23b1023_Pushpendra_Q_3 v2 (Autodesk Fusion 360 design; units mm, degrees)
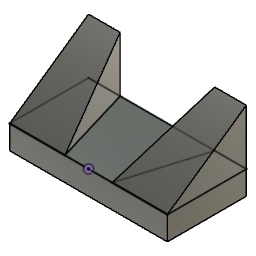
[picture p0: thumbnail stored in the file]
sketch "Sketch1" plane through (0, 0, 0) normal (0, 0, 1) x axis (1, 0, 0)
  line L1 (50, 50) -> (-50, 50)
  line L2 (-50, 0) -> (-50, 50)
  line L3 (50, 0) -> (-50, 0)
  line L4 (50, 0) -> (50, 50)
  line L5 (-30, 50) -> (-50, 50)
  line L6 (30, 50) -> (50, 50)
  line L7 (-15, 0) -> (-50, 0)
  line L8 (15, 0) -> (50, 0)
  line L9 (-30, 50) -> (-15, 0)
  line L10 (30, 50) -> (15, 0)
  point P6 (-30, 50)
  point P7 (30, 50)
  point P8 (-15, 0)
  point P9 (15, 0)
  point P2 (-50, 50)
  point P3 (50, 50)
  point P4 (-50, 0)
  point P5 (50, 0)
  point P1 (0, 0)
  horizontal L1
  perpendicular L1 L2
  perpendicular L2 L3
  perpendicular L3 L4
  coincident L1 P6
  coincident L1 P7
  coincident L3 P8
  coincident L3 P9
  dimension "d1" distance P2 P3 = 100
  dimension "d2" distance P3 P7 = 20
  dimension "d3" distance P2 P6 = 20
  dimension "d4" distance P4 P8 = 35
  dimension "d5" distance P5 P9 = 35
  dimension "d6" distance P1 L1 = 50
  dimension "d7" distance P1 L4 = 50
  dimension "d8" distance P1 L9 = 14.3674
extrude "Extrude1" new body sketch "Sketch1" along normal blind 35
extrude "Extrude3" add sketch "Sketch1" against normal blind 15
sketch "Sketch2" plane through (-50, 0, 0) normal (-1, 0, 0) x axis (0, -1, 0)
  line L1 (0, 35) -> (0, -15)
  line L2 (-50, 35) -> (0, 35)
  line L3 (-50, -15) -> (-50, 35)
  line L4 (0, -15) -> (-50, -15)
  line L5 (0, 0) -> (-50, 35)
  point P4 (-50, 35)
  point P6 (-50, 35)
  point P1 (0, 0)
  point P7 (0, 0)
  coincident P4 P6
  coincident P1 P7
sketch "Sketch3" plane through (50, 0, 0) normal (1, 0, 0) x axis (0, 1, 0)
  line L1 (50, 35) -> (50, -15)
  line L2 (0, 35) -> (50, 35)
  line L3 (0, -15) -> (0, 35)
  line L4 (50, -15) -> (0, -15)
  line L5 (0, 0) -> (50, 35)
  point P3 (50, 35)
  point P6 (50, 35)
  point P1 (0, 0)
  point P7 (0, 0)
  coincident P3 P6
  coincident P1 P7
extrude "Extrude4" cut sketch "Sketch3" profile of L2 L3 L5 against normal blind 35
extrude "Extrude5" cut sketch "Sketch2" profile of L1 L2 L5 against normal blind 35
extrude "Extrude2" add sketch "Sketch1" against normal blind 15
